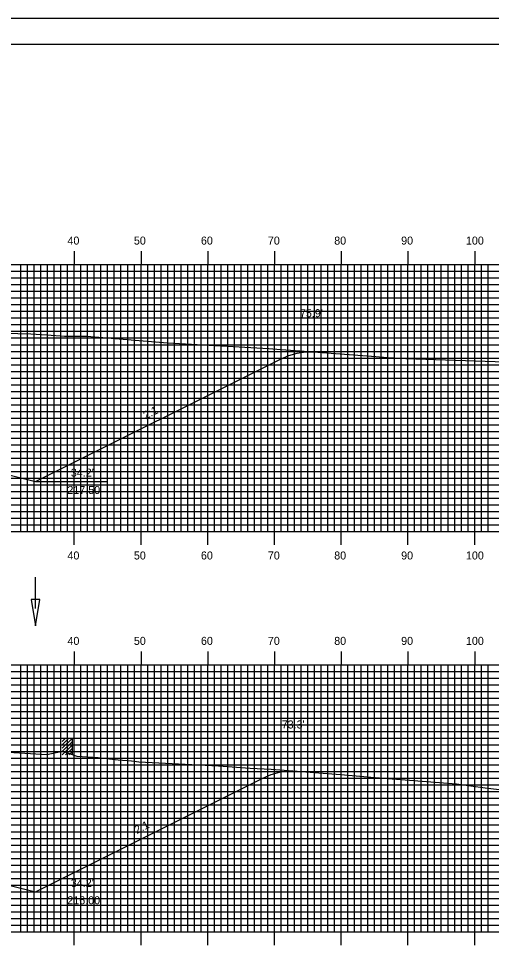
# Model space of a CAD drawing. Extents: x 1816489 to 1816833, y 442591 to 442811.
# Drawn here: x 1816686.7 to 1816757.6, y 442671.2 to 442810.5 of the extents above; entities that cross this region are included whole.
import ezdxf

# ---------------------------------------------------------------- set-up
doc = ezdxf.new("R2010")
doc.units = 0
for name, color, linetype in [('ANNOTATION', 7, 'Continuous'), ('BORDER', 7, 'Continuous'), ('D_Drainage_Ditch_Line', 7, 'Continuous'), ('D_Roadway_Centerline', 7, 'Continuous'), ('D_Roadway_SlopeLines', 7, 'Continuous'), ('D_Text_Standard', 7, 'Continuous'), ('H_V ANNOTATION', 7, 'Continuous'), ('M_Buildings_Rooftop', 7, 'Continuous'), ('MAJOR', 7, 'Continuous'), ('MINOR', 7, 'Continuous'), ('PDRAIN', 7, 'Continuous'), ('PLOT BOUNDARY', 7, 'Continuous'), ('S_Roadway_Centerline', 7, 'Continuous')]:
    doc.layers.add(name, color=color, linetype=linetype)

msp = doc.modelspace()

# ---------------------------------------------------------------- linework, layer by layer
at = {"layer": 'BORDER'}
msp.add_lwpolyline([(1816505.47, 442596.67), (1816825.47, 442596.67), (1816825.47, 442806.67), (1816505.47, 442806.67)], close=True, dxfattribs=at)
at = {"layer": 'D_Drainage_Ditch_Line'}
msp.add_line((1816689.25, 442722.13), (1816689.25, 442726.83), dxfattribs=at)
msp.add_lwpolyline([(1816689.9, 442723.45), (1816688.59, 442723.45), (1816689.25, 442719.51)], close=True, dxfattribs=at)
at = {"layer": 'D_Roadway_Centerline'}
for points in [[(1816567.06, 442766.87), (1816568.31, 442766.78), (1816569.56, 442766.53), (1816570.81, 442766.13), (1816572.06, 442765.58), (1816620.9, 442741.17), (1816624.9, 442742.17), (1816635.07, 442744.71), (1816643.07, 442745.03), (1816655.07, 442745.27), (1816667.07, 442745.03), (1816675.07, 442744.71), (1816685.25, 442742.17), (1816689.25, 442741.17), (1816725.96, 442759.52), (1816727.21, 442760.06), (1816728.46, 442760.41), (1816729.71, 442760.59), (1816730.96, 442760.58)], [(1816566.01, 442705.89), (1816567.26, 442705.8), (1816568.51, 442705.55), (1816569.76, 442705.16), (1816571.01, 442704.61), (1816620.9, 442679.67), (1816624.9, 442680.67), (1816635.07, 442683.21), (1816643.07, 442683.53), (1816655.07, 442683.77), (1816667.07, 442683.53), (1816675.07, 442683.21), (1816685.25, 442680.67), (1816689.25, 442679.67), (1816723.34, 442696.71), (1816724.59, 442697.25), (1816725.84, 442697.6), (1816727.09, 442697.77), (1816728.34, 442697.76)]]:
    msp.add_lwpolyline(points, dxfattribs=at)
at = {"layer": 'D_Roadway_SlopeLines'}
for points in [[(1816689.25, 442741.17), (1816725.96, 442759.52), (1816727.21, 442760.06), (1816728.46, 442760.41), (1816729.71, 442760.59), (1816730.96, 442760.58)], [(1816675.07, 442744.71), (1816689.25, 442741.17)], [(1816689.25, 442679.67), (1816723.34, 442696.71), (1816724.59, 442697.25), (1816725.84, 442697.6), (1816727.09, 442697.77), (1816728.34, 442697.76)], [(1816675.07, 442683.21), (1816689.25, 442679.67)]]:
    msp.add_lwpolyline(points, dxfattribs=at)
at = {"layer": 'M_Buildings_Rooftop'}
for p, q in [((1816693.27, 442701.2), (1816694.78, 442702.71)), ((1816693.27, 442701.7), (1816694.26, 442702.71)), ((1816693.27, 442702.19), (1816693.77, 442702.71)), ((1816693.27, 442700.71), (1816694.78, 442702.19)), ((1816693.27, 442700.19), (1816694.78, 442701.7)), ((1816694.78, 442700.19), (1816694.78, 442702.71)), ((1816693.77, 442700.19), (1816694.78, 442701.2)), ((1816694.26, 442700.19), (1816694.78, 442700.71))]:
    msp.add_line(p, q, dxfattribs=at)
at = {"layer": 'MAJOR'}
for p, q in [((1816695.07, 442775.67), (1816695.07, 442773.67)), ((1816705.07, 442775.67), (1816705.07, 442773.67)), ((1816715.07, 442775.67), (1816715.07, 442773.67)), ((1816725.07, 442775.67), (1816725.07, 442773.67)), ((1816735.07, 442775.67), (1816735.07, 442773.67)), ((1816745.07, 442775.67), (1816745.07, 442773.67)), ((1816755.07, 442775.67), (1816755.07, 442773.67)), ((1816515.07, 442773.67), (1816795.07, 442773.67)), ((1816515.07, 442773.67), (1816795.07, 442773.67)), ((1816695.07, 442733.67), (1816695.07, 442773.67)), ((1816705.07, 442733.67), (1816705.07, 442773.67)), ((1816715.07, 442733.67), (1816715.07, 442773.67)), ((1816725.07, 442733.67), (1816725.07, 442773.67)), ((1816735.07, 442733.67), (1816735.07, 442773.67)), ((1816745.07, 442733.67), (1816745.07, 442773.67)), ((1816755.07, 442733.67), (1816755.07, 442773.67)), ((1816515.07, 442768.67), (1816795.07, 442768.67)), ((1816515.07, 442763.67), (1816795.07, 442763.67)), ((1816515.07, 442758.67), (1816795.07, 442758.67)), ((1816515.07, 442753.67), (1816795.07, 442753.67)), ((1816515.07, 442748.67), (1816795.07, 442748.67)), ((1816515.07, 442743.67), (1816795.07, 442743.67)), ((1816515.07, 442738.67), (1816795.07, 442738.67)), ((1816515.07, 442733.67), (1816795.07, 442733.67)), ((1816515.07, 442733.67), (1816795.07, 442733.67)), ((1816695.07, 442731.66), (1816695.07, 442733.67)), ((1816705.07, 442731.66), (1816705.07, 442733.67)), ((1816715.07, 442731.66), (1816715.07, 442733.67)), ((1816725.07, 442731.66), (1816725.07, 442733.67)), ((1816735.07, 442731.66), (1816735.07, 442733.67)), ((1816745.07, 442731.66), (1816745.07, 442733.67)), ((1816755.07, 442731.66), (1816755.07, 442733.67)), ((1816695.07, 442715.67), (1816695.07, 442713.67)), ((1816705.07, 442715.67), (1816705.07, 442713.67)), ((1816715.07, 442715.67), (1816715.07, 442713.67)), ((1816725.07, 442715.67), (1816725.07, 442713.67)), ((1816735.07, 442715.67), (1816735.07, 442713.67)), ((1816745.07, 442715.67), (1816745.07, 442713.67)), ((1816755.07, 442715.67), (1816755.07, 442713.67)), ((1816515.07, 442713.67), (1816795.07, 442713.67)), ((1816515.07, 442713.67), (1816795.07, 442713.67)), ((1816695.07, 442673.67), (1816695.07, 442713.67)), ((1816705.07, 442673.67), (1816705.07, 442713.67)), ((1816715.07, 442673.67), (1816715.07, 442713.67)), ((1816725.07, 442673.67), (1816725.07, 442713.67)), ((1816735.07, 442673.67), (1816735.07, 442713.67)), ((1816745.07, 442673.67), (1816745.07, 442713.67)), ((1816755.07, 442673.67), (1816755.07, 442713.67)), ((1816515.07, 442708.67), (1816795.07, 442708.67)), ((1816515.07, 442703.67), (1816795.07, 442703.67)), ((1816515.07, 442698.67), (1816795.07, 442698.67)), ((1816515.07, 442693.67), (1816795.07, 442693.67)), ((1816515.07, 442688.67), (1816795.07, 442688.67)), ((1816515.07, 442683.67), (1816795.07, 442683.67)), ((1816515.07, 442678.67), (1816795.07, 442678.67)), ((1816515.07, 442673.67), (1816795.07, 442673.67)), ((1816515.07, 442673.67), (1816795.07, 442673.67)), ((1816695.07, 442671.66), (1816695.07, 442673.67)), ((1816705.07, 442671.66), (1816705.07, 442673.67)), ((1816715.07, 442671.66), (1816715.07, 442673.67)), ((1816725.07, 442671.66), (1816725.07, 442673.67)), ((1816735.07, 442671.66), (1816735.07, 442673.67)), ((1816745.07, 442671.66), (1816745.07, 442673.67)), ((1816755.07, 442671.66), (1816755.07, 442673.67))]:
    msp.add_line(p, q, dxfattribs=at)
at = {"layer": 'MINOR'}
for p, q in [((1816687.07, 442733.67), (1816687.07, 442773.67)), ((1816688.07, 442733.67), (1816688.07, 442773.67)), ((1816689.07, 442733.67), (1816689.07, 442773.67)), ((1816690.07, 442733.67), (1816690.07, 442773.67)), ((1816691.07, 442733.67), (1816691.07, 442773.67)), ((1816692.07, 442733.67), (1816692.07, 442773.67)), ((1816693.07, 442733.67), (1816693.07, 442773.67)), ((1816694.07, 442733.67), (1816694.07, 442773.67)), ((1816696.07, 442733.67), (1816696.07, 442773.67)), ((1816697.07, 442733.67), (1816697.07, 442773.67)), ((1816698.07, 442733.67), (1816698.07, 442773.67)), ((1816699.07, 442733.67), (1816699.07, 442773.67)), ((1816700.07, 442733.67), (1816700.07, 442773.67)), ((1816701.07, 442733.67), (1816701.07, 442773.67)), ((1816702.07, 442733.67), (1816702.07, 442773.67)), ((1816703.07, 442733.67), (1816703.07, 442773.67)), ((1816704.07, 442733.67), (1816704.07, 442773.67)), ((1816706.07, 442733.67), (1816706.07, 442773.67)), ((1816707.07, 442733.67), (1816707.07, 442773.67)), ((1816708.07, 442733.67), (1816708.07, 442773.67)), ((1816709.07, 442733.67), (1816709.07, 442773.67)), ((1816710.07, 442733.67), (1816710.07, 442773.67)), ((1816711.07, 442733.67), (1816711.07, 442773.67)), ((1816712.07, 442733.67), (1816712.07, 442773.67)), ((1816713.07, 442733.67), (1816713.07, 442773.67)), ((1816714.07, 442733.67), (1816714.07, 442773.67)), ((1816716.07, 442733.67), (1816716.07, 442773.67)), ((1816717.07, 442733.67), (1816717.07, 442773.67)), ((1816718.07, 442733.67), (1816718.07, 442773.67)), ((1816719.07, 442733.67), (1816719.07, 442773.67)), ((1816720.07, 442733.67), (1816720.07, 442773.67)), ((1816721.07, 442733.67), (1816721.07, 442773.67)), ((1816722.07, 442733.67), (1816722.07, 442773.67)), ((1816723.07, 442733.67), (1816723.07, 442773.67)), ((1816724.07, 442733.67), (1816724.07, 442773.67)), ((1816726.07, 442733.67), (1816726.07, 442773.67)), ((1816727.07, 442733.67), (1816727.07, 442773.67)), ((1816728.07, 442733.67), (1816728.07, 442773.67)), ((1816729.07, 442733.67), (1816729.07, 442773.67)), ((1816730.07, 442733.67), (1816730.07, 442773.67)), ((1816731.07, 442733.67), (1816731.07, 442773.67)), ((1816732.07, 442733.67), (1816732.07, 442773.67)), ((1816733.07, 442733.67), (1816733.07, 442773.67)), ((1816734.07, 442733.67), (1816734.07, 442773.67)), ((1816736.07, 442733.67), (1816736.07, 442773.67)), ((1816737.07, 442733.67), (1816737.07, 442773.67)), ((1816738.07, 442733.67), (1816738.07, 442773.67)), ((1816739.07, 442733.67), (1816739.07, 442773.67)), ((1816740.07, 442733.67), (1816740.07, 442773.67)), ((1816741.07, 442733.67), (1816741.07, 442773.67)), ((1816742.07, 442733.67), (1816742.07, 442773.67)), ((1816743.07, 442733.67), (1816743.07, 442773.67)), ((1816744.07, 442733.67), (1816744.07, 442773.67)), ((1816746.07, 442733.67), (1816746.07, 442773.67)), ((1816747.07, 442733.67), (1816747.07, 442773.67)), ((1816748.07, 442733.67), (1816748.07, 442773.67)), ((1816749.07, 442733.67), (1816749.07, 442773.67)), ((1816750.07, 442733.67), (1816750.07, 442773.67)), ((1816751.07, 442733.67), (1816751.07, 442773.67)), ((1816752.07, 442733.67), (1816752.07, 442773.67)), ((1816753.07, 442733.67), (1816753.07, 442773.67)), ((1816754.07, 442733.67), (1816754.07, 442773.67)), ((1816756.07, 442733.67), (1816756.07, 442773.67)), ((1816757.07, 442733.67), (1816757.07, 442773.67)), ((1816515.07, 442772.67), (1816795.07, 442772.67)), ((1816515.07, 442771.67), (1816795.07, 442771.67)), ((1816515.07, 442770.67), (1816795.07, 442770.67)), ((1816515.07, 442769.67), (1816795.07, 442769.67)), ((1816515.07, 442767.67), (1816795.07, 442767.67)), ((1816515.07, 442766.67), (1816795.07, 442766.67)), ((1816515.07, 442765.67), (1816795.07, 442765.67)), ((1816515.07, 442764.67), (1816795.07, 442764.67)), ((1816515.07, 442762.67), (1816795.07, 442762.67)), ((1816515.07, 442761.67), (1816795.07, 442761.67)), ((1816515.07, 442760.67), (1816795.07, 442760.67)), ((1816515.07, 442759.67), (1816795.07, 442759.67)), ((1816515.07, 442757.67), (1816795.07, 442757.67)), ((1816515.07, 442756.67), (1816795.07, 442756.67)), ((1816515.07, 442755.67), (1816795.07, 442755.67)), ((1816515.07, 442754.67), (1816795.07, 442754.67)), ((1816515.07, 442752.67), (1816795.07, 442752.67)), ((1816515.07, 442751.67), (1816795.07, 442751.67)), ((1816515.07, 442750.67), (1816795.07, 442750.67)), ((1816515.07, 442749.67), (1816795.07, 442749.67)), ((1816515.07, 442747.67), (1816795.07, 442747.67)), ((1816515.07, 442746.67), (1816795.07, 442746.67)), ((1816515.07, 442745.67), (1816795.07, 442745.67)), ((1816515.07, 442744.67), (1816795.07, 442744.67)), ((1816515.07, 442742.67), (1816795.07, 442742.67)), ((1816515.07, 442741.67), (1816795.07, 442741.67)), ((1816515.07, 442740.67), (1816795.07, 442740.67)), ((1816515.07, 442739.67), (1816795.07, 442739.67)), ((1816515.07, 442737.67), (1816795.07, 442737.67)), ((1816515.07, 442736.67), (1816795.07, 442736.67)), ((1816515.07, 442735.67), (1816795.07, 442735.67)), ((1816515.07, 442734.67), (1816795.07, 442734.67)), ((1816687.07, 442673.67), (1816687.07, 442713.67)), ((1816688.07, 442673.67), (1816688.07, 442713.67)), ((1816689.07, 442673.67), (1816689.07, 442713.67)), ((1816690.07, 442673.67), (1816690.07, 442713.67)), ((1816691.07, 442673.67), (1816691.07, 442713.67)), ((1816692.07, 442673.67), (1816692.07, 442713.67)), ((1816693.07, 442673.67), (1816693.07, 442713.67)), ((1816694.07, 442673.67), (1816694.07, 442713.67)), ((1816696.07, 442673.67), (1816696.07, 442713.67)), ((1816697.07, 442673.67), (1816697.07, 442713.67)), ((1816698.07, 442673.67), (1816698.07, 442713.67)), ((1816699.07, 442673.67), (1816699.07, 442713.67)), ((1816700.07, 442673.67), (1816700.07, 442713.67)), ((1816701.07, 442673.67), (1816701.07, 442713.67)), ((1816702.07, 442673.67), (1816702.07, 442713.67)), ((1816703.07, 442673.67), (1816703.07, 442713.67)), ((1816704.07, 442673.67), (1816704.07, 442713.67)), ((1816706.07, 442673.67), (1816706.07, 442713.67)), ((1816707.07, 442673.67), (1816707.07, 442713.67)), ((1816708.07, 442673.67), (1816708.07, 442713.67)), ((1816709.07, 442673.67), (1816709.07, 442713.67)), ((1816710.07, 442673.67), (1816710.07, 442713.67)), ((1816711.07, 442673.67), (1816711.07, 442713.67)), ((1816712.07, 442673.67), (1816712.07, 442713.67)), ((1816713.07, 442673.67), (1816713.07, 442713.67)), ((1816714.07, 442673.67), (1816714.07, 442713.67)), ((1816716.07, 442673.67), (1816716.07, 442713.67)), ((1816717.07, 442673.67), (1816717.07, 442713.67)), ((1816718.07, 442673.67), (1816718.07, 442713.67)), ((1816719.07, 442673.67), (1816719.07, 442713.67)), ((1816720.07, 442673.67), (1816720.07, 442713.67)), ((1816721.07, 442673.67), (1816721.07, 442713.67)), ((1816722.07, 442673.67), (1816722.07, 442713.67)), ((1816723.07, 442673.67), (1816723.07, 442713.67)), ((1816724.07, 442673.67), (1816724.07, 442713.67)), ((1816726.07, 442673.67), (1816726.07, 442713.67)), ((1816727.07, 442673.67), (1816727.07, 442713.67)), ((1816728.07, 442673.67), (1816728.07, 442713.67)), ((1816729.07, 442673.67), (1816729.07, 442713.67)), ((1816730.07, 442673.67), (1816730.07, 442713.67)), ((1816731.07, 442673.67), (1816731.07, 442713.67)), ((1816732.07, 442673.67), (1816732.07, 442713.67)), ((1816733.07, 442673.67), (1816733.07, 442713.67)), ((1816734.07, 442673.67), (1816734.07, 442713.67)), ((1816736.07, 442673.67), (1816736.07, 442713.67)), ((1816737.07, 442673.67), (1816737.07, 442713.67)), ((1816738.07, 442673.67), (1816738.07, 442713.67)), ((1816739.07, 442673.67), (1816739.07, 442713.67)), ((1816740.07, 442673.67), (1816740.07, 442713.67)), ((1816741.07, 442673.67), (1816741.07, 442713.67)), ((1816742.07, 442673.67), (1816742.07, 442713.67)), ((1816743.07, 442673.67), (1816743.07, 442713.67)), ((1816744.07, 442673.67), (1816744.07, 442713.67)), ((1816746.07, 442673.67), (1816746.07, 442713.67)), ((1816747.07, 442673.67), (1816747.07, 442713.67)), ((1816748.07, 442673.67), (1816748.07, 442713.67)), ((1816749.07, 442673.67), (1816749.07, 442713.67)), ((1816750.07, 442673.67), (1816750.07, 442713.67)), ((1816751.07, 442673.67), (1816751.07, 442713.67)), ((1816752.07, 442673.67), (1816752.07, 442713.67)), ((1816753.07, 442673.67), (1816753.07, 442713.67)), ((1816754.07, 442673.67), (1816754.07, 442713.67)), ((1816756.07, 442673.67), (1816756.07, 442713.67)), ((1816757.07, 442673.67), (1816757.07, 442713.67)), ((1816515.07, 442712.67), (1816795.07, 442712.67)), ((1816515.07, 442711.67), (1816795.07, 442711.67)), ((1816515.07, 442710.67), (1816795.07, 442710.67)), ((1816515.07, 442709.67), (1816795.07, 442709.67)), ((1816515.07, 442707.67), (1816795.07, 442707.67)), ((1816515.07, 442706.67), (1816795.07, 442706.67)), ((1816515.07, 442705.67), (1816795.07, 442705.67)), ((1816515.07, 442704.67), (1816795.07, 442704.67)), ((1816515.07, 442702.67), (1816795.07, 442702.67)), ((1816515.07, 442701.67), (1816795.07, 442701.67)), ((1816515.07, 442700.67), (1816795.07, 442700.67)), ((1816515.07, 442699.67), (1816795.07, 442699.67)), ((1816515.07, 442697.67), (1816795.07, 442697.67)), ((1816515.07, 442696.67), (1816795.07, 442696.67)), ((1816515.07, 442695.67), (1816795.07, 442695.67)), ((1816515.07, 442694.67), (1816795.07, 442694.67)), ((1816515.07, 442692.67), (1816795.07, 442692.67)), ((1816515.07, 442691.67), (1816795.07, 442691.67)), ((1816515.07, 442690.67), (1816795.07, 442690.67)), ((1816515.07, 442689.67), (1816795.07, 442689.67)), ((1816515.07, 442687.67), (1816795.07, 442687.67)), ((1816515.07, 442686.67), (1816795.07, 442686.67)), ((1816515.07, 442685.67), (1816795.07, 442685.67)), ((1816515.07, 442684.67), (1816795.07, 442684.67)), ((1816515.07, 442682.67), (1816795.07, 442682.67)), ((1816515.07, 442681.67), (1816795.07, 442681.67)), ((1816515.07, 442680.67), (1816795.07, 442680.67)), ((1816515.07, 442679.67), (1816795.07, 442679.67)), ((1816515.07, 442677.67), (1816795.07, 442677.67)), ((1816515.07, 442676.67), (1816795.07, 442676.67)), ((1816515.07, 442675.67), (1816795.07, 442675.67)), ((1816515.07, 442674.67), (1816795.07, 442674.67))]:
    msp.add_line(p, q, dxfattribs=at)
at = {"layer": 'PDRAIN'}
for p, q in [((1816689.25, 442741.17), (1816700.02, 442741.17)), ((1816689.25, 442679.67), (1816700.02, 442679.67))]:
    msp.add_line(p, q, dxfattribs=at)
at = {"layer": 'PLOT BOUNDARY'}
msp.add_lwpolyline([(1816489.29, 442590.55), (1816829.29, 442590.55), (1816829.29, 442810.55), (1816489.29, 442810.55)], close=True, dxfattribs=at)
at = {"layer": 'S_Roadway_Centerline'}
for points in [[(1816684.67, 442763.38), (1816688.54, 442763.29), (1816690.96, 442763.15), (1816693.6, 442762.92), (1816696.97, 442762.92), (1816709.06, 442761.95), (1816724.24, 442761.08), (1816725.42, 442761), (1816730.22, 442760.64), (1816740.26, 442759.88), (1816741.95, 442759.77), (1816744.76, 442759.61), (1816759.65, 442759.11), (1816769.56, 442758.48), (1816776.48, 442758.16), (1816792.33, 442757.36), (1816793.3, 442757.27), (1816793.89, 442757.24), (1816795.07, 442757.09)], [(1816678.58, 442701.01), (1816690.94, 442700.24), (1816693.32, 442700.75), (1816695.45, 442699.98), (1816698.67, 442699.81), (1816701.63, 442699.46), (1816703.64, 442699.27), (1816704.72, 442699.13), (1816716.67, 442698.53), (1816721.45, 442698.19), (1816724.58, 442698.06), (1816734.94, 442697.24), (1816738.44, 442696.94), (1816739.5, 442696.86), (1816752.33, 442695.86), (1816756.62, 442695.24), (1816765.53, 442694.2), (1816772.99, 442693.6), (1816778.73, 442693.04), (1816789.41, 442691.82), (1816791.91, 442691.6), (1816795.07, 442691.25)]]:
    msp.add_lwpolyline(points, dxfattribs=at)

# ---------------------------------------------------------------- texts
at = {"layer": 'ANNOTATION'}
for p in [(1816705.75, 442750.45), (1816704.44, 442688.3)]:
    msp.add_text('2:1', height=1.2, rotation=26.5651, dxfattribs=at).set_placement(p)
for s, p in [("34.2'", (1816694.56, 442741.89)), ('217.50', (1816694.04, 442739.29)), ("34.2'", (1816694.56, 442680.39)), ('216.00', (1816694.03, 442677.79))]:
    msp.add_text(s, height=1.2, dxfattribs=at).set_placement(p)
at = {"layer": 'D_Text_Standard'}
for s, p in [("75.9'", (1816728.88, 442765.79)), ("73.3'", (1816726.15, 442704.14))]:
    msp.add_text(s, height=1.2, dxfattribs=at).set_placement(p)
at = {"layer": 'H_V ANNOTATION'}
for s, p in [('40', (1816694.05, 442776.67)), ('50', (1816704, 442776.67)), ('60', (1816714.05, 442776.67)), ('70', (1816724.08, 442776.67)), ('80', (1816734.02, 442776.67)), ('90', (1816744.05, 442776.67)), ('100', (1816753.76, 442776.67)), ('40', (1816694.05, 442729.47)), ('50', (1816704, 442729.47)), ('60', (1816714.05, 442729.47)), ('70', (1816724.08, 442729.47)), ('80', (1816734.02, 442729.47)), ('90', (1816744.05, 442729.47)), ('100', (1816753.76, 442729.47)), ('40', (1816694.05, 442716.67)), ('50', (1816704, 442716.67)), ('60', (1816714.05, 442716.67)), ('70', (1816724.08, 442716.67)), ('80', (1816734.02, 442716.67)), ('90', (1816744.05, 442716.67)), ('100', (1816753.76, 442716.67))]:
    msp.add_text(s, height=1.2, dxfattribs=at).set_placement(p)

doc.saveas('drawing.dxf')
